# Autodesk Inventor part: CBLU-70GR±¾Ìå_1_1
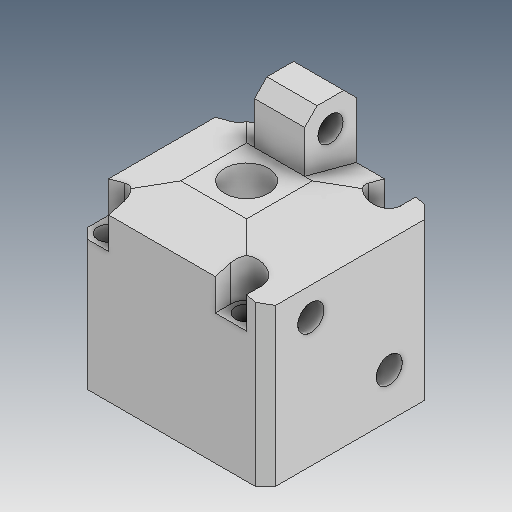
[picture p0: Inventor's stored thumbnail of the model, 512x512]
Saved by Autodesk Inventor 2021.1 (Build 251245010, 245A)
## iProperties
Created: 2019-04
Part Number: CBLU-70GR±¾Ìå_1_1
Material: Ogólny
Document SubType Name: Modeling
Designer: user
Density: 1 g/cm^3
Appearance: Domyślna
Author: user
Revision Number: ÈÎºÎ
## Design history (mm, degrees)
feature "N"
feature "Í¹Ì¨-À­Éì2"
node "Bryła1"
node "Bryła2"
